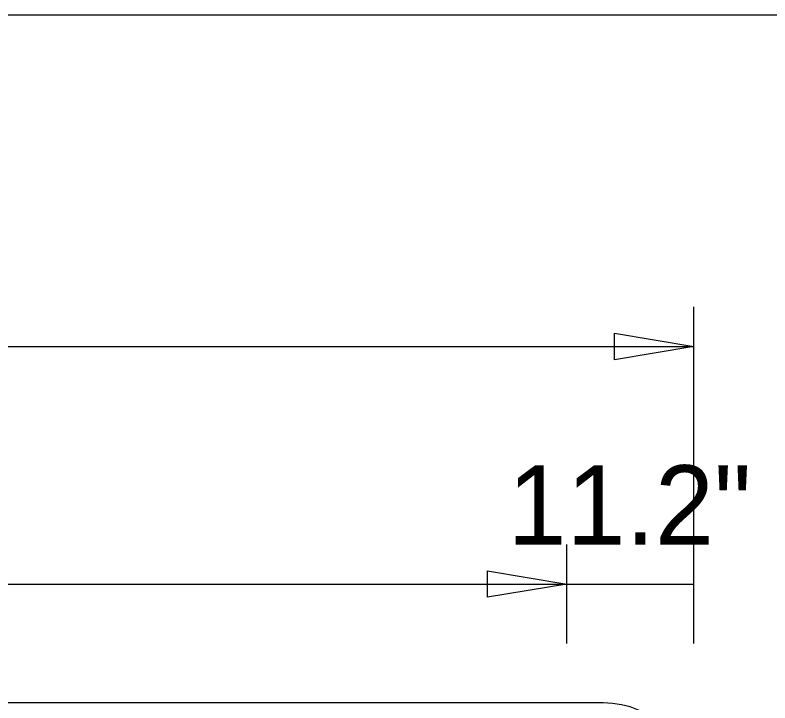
# Model space of a CAD drawing. Extents: x 2149934 to 2150188, y 145113 to 145238.
# Drawn here: x 2150100.78 to 2150106.34, y 145161.88 to 145166.95 of the extents above; entities that cross this region are included whole.
import ezdxf

# ---------------------------------------------------------------- set-up
doc = ezdxf.new("R2010")
doc.units = 0
for name, color, linetype in [('GSBWFILL', 7, 'Continuous'), ('GSCOLORFILL', 7, 'Continuous'), ('GSDIMS', 7, 'Continuous'), ('GSOUTLINE', 7, 'Continuous'), ('Level 1', 7, 'Continuous')]:
    doc.layers.add(name, color=color, linetype=linetype)

msp = doc.modelspace()

# ---------------------------------------------------------------- linework, layer by layer
at = {"layer": 'GSBWFILL'}
msp.add_line((2150105.112, 145161.8839), (2150093.4449, 145161.8839), dxfattribs=at)
msp.add_arc((2150105.112, 145161.2172), 0.6667, 0, 90, dxfattribs=at)
at = {"layer": 'GSCOLORFILL'}
msp.add_line((2150105.112, 145161.8839), (2150093.4449, 145161.8839), dxfattribs=at)
msp.add_line((2150105.112, 145161.8839), (2150093.4449, 145161.8839), dxfattribs=at)
msp.add_line((2150105.112, 145161.8839), (2150093.4449, 145161.8839), dxfattribs=at)
msp.add_arc((2150105.112, 145161.2172), 0.6667, 0, 90, dxfattribs=at)
msp.add_arc((2150105.112, 145161.2172), 0.6667, 0, 90, dxfattribs=at)
msp.add_arc((2150105.112, 145161.2172), 0.6667, 0, 90, dxfattribs=at)
at = {"layer": 'GSDIMS'}
for p, q in [((2150105.7788, 145164.0714), (2150105.7788, 145164.8006)), ((2150092.7782, 145164.5089), (2150105.7788, 145164.5089)), ((2150105.7788, 145162.3214), (2150105.7788, 145164.0714)), ((2150104.8445, 145162.3214), (2150104.8445, 145163.0506)), ((2150104.8445, 145162.3214), (2150104.8445, 145163.0506)), ((2150105.7788, 145162.3214), (2150105.7788, 145163.0506)), ((2150094.0283, 145162.7589), (2150104.8445, 145162.7589)), ((2150104.8445, 145162.7589), (2150105.7788, 145162.7589))]:
    msp.add_line(p, q, dxfattribs=at)
for points in [[(2150105.7788, 145164.5089), (2150105.1955, 145164.4117), (2150105.1955, 145164.6061)], [(2150104.8445, 145162.7589), (2150104.2612, 145162.6617), (2150104.2612, 145162.8561)]]:
    msp.add_lwpolyline(points, close=True, dxfattribs=at)
at = {"layer": 'GSOUTLINE'}
msp.add_line((2150105.112, 145161.8839), (2150093.4449, 145161.8839), dxfattribs=at)
msp.add_arc((2150105.112, 145161.2172), 0.6667, 0, 90, dxfattribs=at)
at = {"layer": 'Level 1'}
msp.add_line((2150135.4472, 145166.9499), (2150017.5574, 145166.9499), dxfattribs=at)

# ---------------------------------------------------------------- texts
at = {"layer": 'GSDIMS'}
msp.add_text('11.2"', height=0.58333, dxfattribs=at).set_placement((2150104.4093, 145163.0506))

doc.saveas('drawing.dxf')
